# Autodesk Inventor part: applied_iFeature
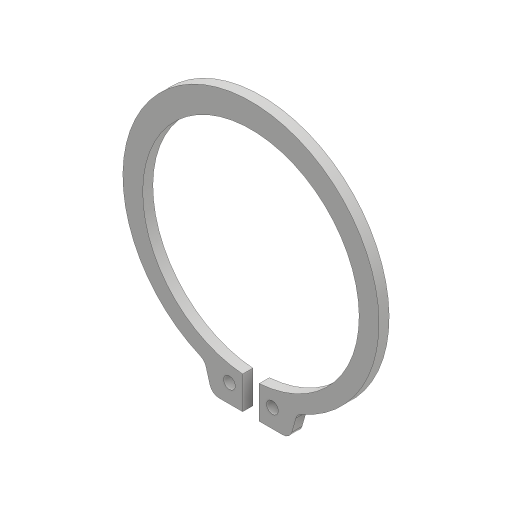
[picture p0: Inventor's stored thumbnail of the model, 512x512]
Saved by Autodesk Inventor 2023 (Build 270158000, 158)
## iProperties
Created: 2016-06
Part Number: applied_iFeature
Material: Generic
Document SubType Name: Modeling
Designer: CADCIM
Density: 1 g/cm^3
Appearance: Default
Author: CADCIM
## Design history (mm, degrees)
sketch "Sketch1"
  geometry: L1 (9.52, -25.305)-(8.665, -28.284); L2 (6.743, -29.733)-(1.75, -29.733); L3 (1.75, -29.733)-(1.75, -22.833); L4 (0, 0)-(0, -33.55); L5 (-6.743, -29.733)-(-1.75, -29.733); L6 (-1.75, -29.733)-(-1.75, -22.833); L7 (-9.52, -25.305)-(-8.665, -28.284); C1 r 1.25 at (4.55, -25.815); C2 r 1.25 at (-4.55, -25.815); A1 r 22.9 centre (0, 0) between (1.75, -22.833) and (-1.75, -22.833); A2 r 27.1 centre (0, 0.9) between (10.656, -24.017) and (-10.656, -24.017); A3 r 2 centre (-6.743, -27.733) between (-8.665, -28.284) and (-6.743, -29.733); A4 r 2 centre (-11.442, -25.856) between (-9.52, -25.305) and (-10.656, -24.017); A5 r 2 centre (11.442, -25.856) between (10.656, -24.017) and (9.52, -25.305); A6 r 2 centre (6.743, -27.733) between (6.743, -29.733) and (8.665, -28.284); 12 further points
  constraints: 18 point on circle, 14 end point, 8 centre point, 8 point on line, 8 tangent, 4 equal radius, 4 symmetric about line, 2 coincident, 2 midpoint, 1 horizontal, 1 horizontal alignment, 1 perpendicular, 1 vertical
  dimensions: "d0" = 45.8 diameter of A1; "d4" = 6.9 distance from line of L6.end L5; "d5" = 5.1 distance of point (0, 28) point (0, 22.9); "d6" = 2.5 diameter of C1; "d8" = 2 radius of A3 (derived); "d9" = 2.8 distance from line of C1.centre L3; "d10" = 3.5 distance of L5.end L2.end; "d11" = 27.1 radius of A2; "d14" = 6.5 distance of L5.end point (-8.25, -29.733); "d15" = 32 deg angle of L7 L1
extrude "Extrusion1" new body sketch "Sketch1" distance "d16" = 2.15; taper "d17" = 0 deg
body "Solid1"
